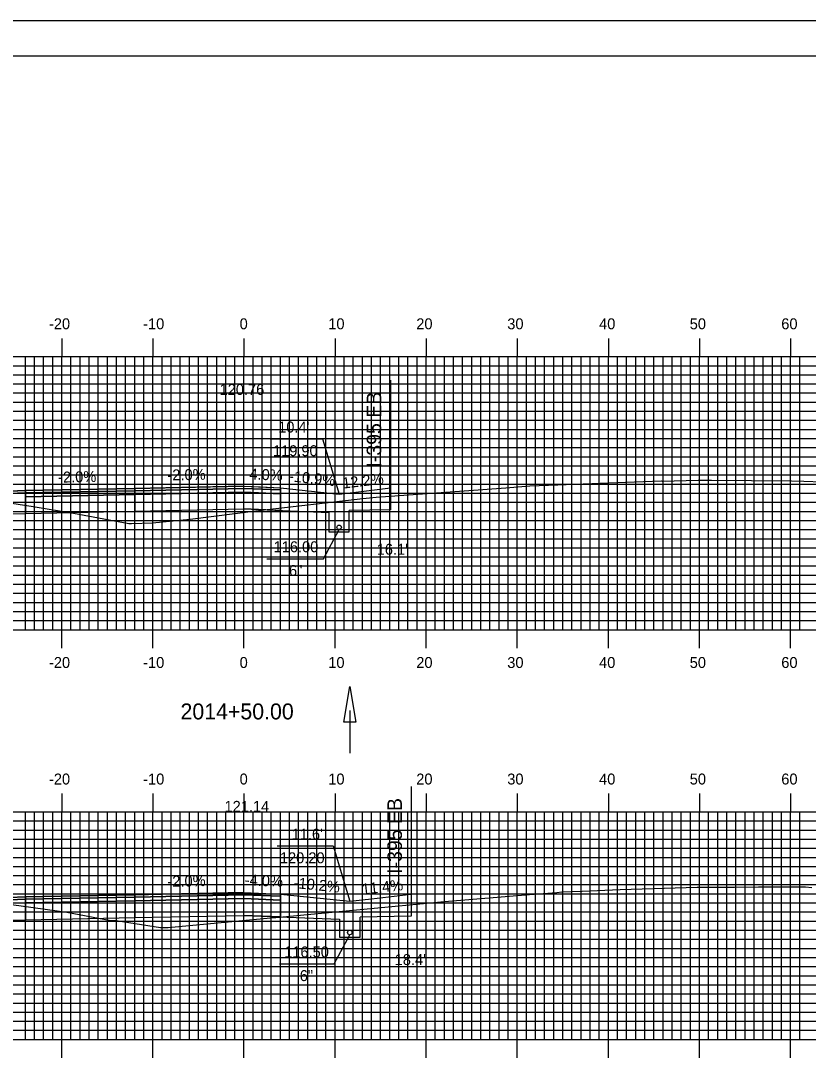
# Model space of a CAD drawing. Extents: x 854287 to 854631, y 366605 to 366825.
# Drawn here: x 854428.5 to 854515, y 366710.6 to 366824.9 of the extents above; entities that cross this region are included whole.
import ezdxf

# ---------------------------------------------------------------- set-up
doc = ezdxf.new("R2010")
doc.units = 0
for name, color, linetype in [('ANNOTATION', 7, 'Continuous'), ('BORDER', 7, 'Continuous'), ('D_Drainage_Ditch_Line', 7, 'Continuous'), ('D_Roadway_Centerline', 7, 'Continuous'), ('D_Roadway_Centerline_Text', 7, 'Continuous'), ('D_Roadway_Edge_Shoulder', 7, 'Continuous'), ('D_Roadway_Edge_TW', 7, 'Continuous'), ('D_Roadway_Pavement', 7, 'Continuous'), ('D_Roadway_SubGrade', 7, 'Continuous'), ('D_Text_Standard', 7, 'Continuous'), ('H_V ANNOTATION', 7, 'Continuous'), ('M_Roadway_Centerline', 7, 'Continuous'), ('MAJOR', 7, 'Continuous'), ('MINOR', 7, 'Continuous'), ('PDRAIN', 7, 'Continuous'), ('PLOT BOUNDARY', 7, 'Continuous'), ('S_Roadway_Centerline', 7, 'Continuous')]:
    doc.layers.add(name, color=color, linetype=linetype)

msp = doc.modelspace()

# ---------------------------------------------------------------- linework, layer by layer
at = {"layer": 'ANNOTATION'}
for points in [[(854455.93, 366779.04), (854461.66, 366779.04), (854463.48, 366772.96)], [(854455.53, 366765.85), (854461.75, 366765.85), (854463.48, 366769.06)], [(854456.69, 366734.34), (854462.84, 366734.34), (854464.66, 366728.25)], [(854456.93, 366721.35), (854462.93, 366721.35), (854464.66, 366724.56)]]:
    msp.add_lwpolyline(points, dxfattribs=at)
at = {"layer": 'BORDER'}
msp.add_lwpolyline([(854303.44, 366611.06), (854623.44, 366611.06), (854623.44, 366821.06), (854303.44, 366821.06)], close=True, dxfattribs=at)
at = {"layer": 'D_Drainage_Ditch_Line'}
msp.add_line((854464.66, 366749.2), (854464.66, 366744.5), dxfattribs=at)
msp.add_lwpolyline([(854465.32, 366747.89), (854464, 366747.89), (854464.66, 366751.83)], close=True, dxfattribs=at)
at = {"layer": 'D_Roadway_Centerline'}
for p, q in [((854453.04, 366771.32), (854462.35, 366770.95)), ((854469.12, 366771.23), (854464.6, 366771.14)), ((854453.04, 366726.69), (854463.53, 366726.27)), ((854471.39, 366726.6), (854465.78, 366726.49))]:
    msp.add_line(p, q, dxfattribs=at)
for points in [[(854370.14, 366772.7), (854370.15, 366772.7), (854406.87, 366769.48), (854410.14, 366770.29), (854410.15, 366770.29), (854421.04, 366773.02), (854421.05, 366773.02), (854423.89, 366773.13), (854429.04, 366773.34), (854429.04, 366773.34), (854441.04, 366773.58), (854441.04, 366773.58), (854449.37, 366773.75), (854453.04, 366773.82), (854454.84, 366773.75), (854457.04, 366773.66), (854463.48, 366772.96), (854463.48, 366772.96)], [(854457.04, 366773.66), (854463.48, 366772.96)], [(854463.48, 366772.96), (854465.32, 366773.18), (854469.12, 366773.65)], [(854374.32, 366728.87), (854406.87, 366724.85), (854409.62, 366725.54), (854410.14, 366725.67), (854421.04, 366728.39), (854422.63, 366728.46), (854429.04, 366728.71), (854429.04, 366728.71), (854429.05, 366728.71), (854441.04, 366728.95), (854447.09, 366729.07), (854453.04, 366729.19), (854453.58, 366729.17), (854457.04, 366729.03), (854464.66, 366728.25)], [(854457.04, 366729.03), (854464.66, 366728.25)], [(854464.66, 366728.25), (854467.03, 366728.52), (854471.39, 366729.02)]]:
    msp.add_lwpolyline(points, dxfattribs=at)
at = {"layer": 'D_Roadway_Edge_Shoulder'}
for points in [[(854453.04, 366773.82), (854457.04, 366773.66), (854457.04, 366773.41), (854453.04, 366773.57)], [(854429.04, 366773.34), (854421.04, 366773.02), (854421.04, 366772.77), (854429.04, 366773.09)], [(854453.04, 366729.19), (854457.04, 366729.03), (854457.04, 366728.78), (854453.04, 366728.94)], [(854429.04, 366728.71), (854421.04, 366728.39), (854421.04, 366728.14), (854429.04, 366728.46)]]:
    msp.add_lwpolyline(points, close=True, dxfattribs=at)
at = {"layer": 'D_Roadway_Edge_TW'}
for points in [[(854453.04, 366773.82), (854441.04, 366773.58), (854441.04, 366773.33), (854453.04, 366773.57)], [(854441.04, 366773.58), (854429.04, 366773.34), (854429.04, 366773.09), (854441.04, 366773.33)], [(854453.04, 366729.19), (854441.04, 366728.95), (854441.04, 366728.7), (854453.04, 366728.94)], [(854441.04, 366728.95), (854429.04, 366728.71), (854429.04, 366728.46), (854441.04, 366728.7)]]:
    msp.add_lwpolyline(points, close=True, dxfattribs=at)
at = {"layer": 'D_Roadway_Pavement'}
for points in [[(854441.04, 366773.33), (854429.04, 366773.09), (854429.04, 366772.67), (854441.04, 366772.91)], [(854453.04, 366773.57), (854441.04, 366773.33), (854441.04, 366772.91), (854453.04, 366773.15)], [(854453.04, 366773.57), (854457.04, 366773.41), (854457.04, 366772.99), (854453.04, 366773.15)], [(854441.04, 366728.7), (854429.04, 366728.46), (854429.04, 366728.05), (854441.04, 366728.29)], [(854453.04, 366728.94), (854441.04, 366728.7), (854441.04, 366728.29), (854453.04, 366728.53)], [(854453.04, 366728.94), (854457.04, 366728.78), (854457.04, 366728.37), (854453.04, 366728.53)]]:
    msp.add_lwpolyline(points, close=True, dxfattribs=at)
for points in [[(854429.04, 366773.09), (854429.04, 366772.67)], [(854429.04, 366773.09), (854429.04, 366772.67)], [(854441.04, 366773.33), (854441.04, 366772.91)], [(854429.04, 366728.46), (854429.04, 366728.05)], [(854429.04, 366728.46), (854429.04, 366728.05)], [(854441.04, 366728.7), (854441.04, 366728.29)]]:
    msp.add_lwpolyline(points, dxfattribs=at)
at = {"layer": 'D_Roadway_SubGrade'}
for p, q in [((854469.12, 366785.46), (854469.12, 366771.23)), ((854471.39, 366740.83), (854471.39, 366726.6))]:
    msp.add_line(p, q, dxfattribs=at)
for points in [[(854453.04, 366773.15), (854457.04, 366772.99), (854457.04, 366773.41), (854457.04, 366773.66), (854457.04, 366771.16), (854453.04, 366771.32)], [(854429.04, 366772.67), (854429.04, 366773.09), (854421.04, 366772.77), (854421.04, 366773.02), (854410.87, 366770.48), (854429.04, 366770.84)], [(854441.04, 366772.91), (854429.04, 366772.67), (854429.04, 366770.84), (854441.04, 366771.08)], [(854453.04, 366773.15), (854441.04, 366772.91), (854441.04, 366771.08), (854453.04, 366771.32)], [(854453.04, 366728.53), (854457.04, 366728.37), (854457.04, 366728.78), (854457.04, 366729.03), (854457.04, 366726.53), (854453.04, 366726.69)], [(854429.04, 366728.05), (854429.04, 366728.46), (854421.04, 366728.14), (854421.04, 366728.39), (854410.87, 366725.85), (854429.04, 366726.21)], [(854441.04, 366728.29), (854429.04, 366728.05), (854429.04, 366726.21), (854441.04, 366726.45)], [(854453.04, 366728.53), (854441.04, 366728.29), (854441.04, 366726.45), (854453.04, 366726.69)]]:
    msp.add_lwpolyline(points, close=True, dxfattribs=at)
at = {"layer": 'MAJOR'}
for p, q in [((854433.04, 366790.06), (854433.04, 366788.06)), ((854443.04, 366790.06), (854443.04, 366788.06)), ((854453.04, 366790.06), (854453.04, 366788.06)), ((854463.04, 366790.06), (854463.04, 366788.06)), ((854473.04, 366790.06), (854473.04, 366788.06)), ((854483.04, 366790.06), (854483.04, 366788.06)), ((854493.04, 366790.06), (854493.04, 366788.06)), ((854503.04, 366790.06), (854503.04, 366788.06)), ((854513.04, 366790.06), (854513.04, 366788.06)), ((854313.04, 366788.06), (854593.04, 366788.06)), ((854313.04, 366788.06), (854593.04, 366788.06)), ((854433.04, 366758.06), (854433.04, 366788.06)), ((854443.04, 366758.06), (854443.04, 366788.06)), ((854453.04, 366758.06), (854453.04, 366788.06)), ((854463.04, 366758.06), (854463.04, 366788.06)), ((854473.04, 366758.06), (854473.04, 366788.06)), ((854483.04, 366758.06), (854483.04, 366788.06)), ((854493.04, 366758.06), (854493.04, 366788.06)), ((854503.04, 366758.06), (854503.04, 366788.06)), ((854513.04, 366758.06), (854513.04, 366788.06)), ((854313.04, 366783.06), (854593.04, 366783.06)), ((854313.04, 366778.06), (854593.04, 366778.06)), ((854313.04, 366773.06), (854593.04, 366773.06)), ((854313.04, 366768.06), (854593.04, 366768.06)), ((854313.04, 366763.06), (854593.04, 366763.06)), ((854313.04, 366758.06), (854593.04, 366758.06)), ((854313.04, 366758.06), (854593.04, 366758.06)), ((854433.04, 366756.05), (854433.04, 366758.06)), ((854443.04, 366756.05), (854443.04, 366758.06)), ((854453.04, 366756.05), (854453.04, 366758.06)), ((854463.04, 366756.05), (854463.04, 366758.06)), ((854473.04, 366756.05), (854473.04, 366758.06)), ((854483.04, 366756.05), (854483.04, 366758.06)), ((854493.04, 366756.05), (854493.04, 366758.06)), ((854503.04, 366756.05), (854503.04, 366758.06)), ((854513.04, 366756.05), (854513.04, 366758.06)), ((854433.04, 366740.06), (854433.04, 366738.06)), ((854443.04, 366740.06), (854443.04, 366738.06)), ((854453.04, 366740.06), (854453.04, 366738.06)), ((854463.04, 366740.06), (854463.04, 366738.06)), ((854473.04, 366740.06), (854473.04, 366738.06)), ((854483.04, 366740.06), (854483.04, 366738.06)), ((854493.04, 366740.06), (854493.04, 366738.06)), ((854503.04, 366740.06), (854503.04, 366738.06)), ((854513.04, 366740.06), (854513.04, 366738.06)), ((854313.04, 366738.06), (854593.04, 366738.06)), ((854313.04, 366738.06), (854593.04, 366738.06)), ((854433.04, 366713.06), (854433.04, 366738.06)), ((854443.04, 366713.06), (854443.04, 366738.06)), ((854453.04, 366713.06), (854453.04, 366738.06)), ((854463.04, 366713.06), (854463.04, 366738.06)), ((854473.04, 366713.06), (854473.04, 366738.06)), ((854483.04, 366713.06), (854483.04, 366738.06)), ((854493.04, 366713.06), (854493.04, 366738.06)), ((854503.04, 366713.06), (854503.04, 366738.06)), ((854513.04, 366713.06), (854513.04, 366738.06)), ((854313.04, 366733.06), (854593.04, 366733.06)), ((854313.04, 366728.06), (854593.04, 366728.06)), ((854313.04, 366723.06), (854593.04, 366723.06)), ((854313.04, 366718.06), (854593.04, 366718.06)), ((854313.04, 366713.06), (854593.04, 366713.06)), ((854313.04, 366713.06), (854593.04, 366713.06)), ((854433.04, 366711.05), (854433.04, 366713.06)), ((854443.04, 366711.05), (854443.04, 366713.06)), ((854453.04, 366711.05), (854453.04, 366713.06)), ((854463.04, 366711.05), (854463.04, 366713.06)), ((854473.04, 366711.05), (854473.04, 366713.06)), ((854483.04, 366711.05), (854483.04, 366713.06)), ((854493.04, 366711.05), (854493.04, 366713.06)), ((854503.04, 366711.05), (854503.04, 366713.06)), ((854513.04, 366711.05), (854513.04, 366713.06))]:
    msp.add_line(p, q, dxfattribs=at)
at = {"layer": 'MINOR'}
for p, q in [((854429.04, 366758.06), (854429.04, 366788.06)), ((854430.04, 366758.06), (854430.04, 366788.06)), ((854431.04, 366758.06), (854431.04, 366788.06)), ((854432.04, 366758.06), (854432.04, 366788.06)), ((854434.04, 366758.06), (854434.04, 366788.06)), ((854435.04, 366758.06), (854435.04, 366788.06)), ((854436.04, 366758.06), (854436.04, 366788.06)), ((854437.04, 366758.06), (854437.04, 366788.06)), ((854438.04, 366758.06), (854438.04, 366788.06)), ((854439.04, 366758.06), (854439.04, 366788.06)), ((854440.04, 366758.06), (854440.04, 366788.06)), ((854441.04, 366758.06), (854441.04, 366788.06)), ((854442.04, 366758.06), (854442.04, 366788.06)), ((854444.04, 366758.06), (854444.04, 366788.06)), ((854445.04, 366758.06), (854445.04, 366788.06)), ((854446.04, 366758.06), (854446.04, 366788.06)), ((854447.04, 366758.06), (854447.04, 366788.06)), ((854448.04, 366758.06), (854448.04, 366788.06)), ((854449.04, 366758.06), (854449.04, 366788.06)), ((854450.04, 366758.06), (854450.04, 366788.06)), ((854451.04, 366758.06), (854451.04, 366788.06)), ((854452.04, 366758.06), (854452.04, 366788.06)), ((854454.04, 366758.06), (854454.04, 366788.06)), ((854455.04, 366758.06), (854455.04, 366788.06)), ((854456.04, 366758.06), (854456.04, 366788.06)), ((854457.04, 366758.06), (854457.04, 366788.06)), ((854458.04, 366758.06), (854458.04, 366788.06)), ((854459.04, 366758.06), (854459.04, 366788.06)), ((854460.04, 366758.06), (854460.04, 366788.06)), ((854461.04, 366758.06), (854461.04, 366788.06)), ((854462.04, 366758.06), (854462.04, 366788.06)), ((854464.04, 366758.06), (854464.04, 366788.06)), ((854465.04, 366758.06), (854465.04, 366788.06)), ((854466.04, 366758.06), (854466.04, 366788.06)), ((854467.04, 366758.06), (854467.04, 366788.06)), ((854468.04, 366758.06), (854468.04, 366788.06)), ((854469.04, 366758.06), (854469.04, 366788.06)), ((854470.04, 366758.06), (854470.04, 366788.06)), ((854471.04, 366758.06), (854471.04, 366788.06)), ((854472.04, 366758.06), (854472.04, 366788.06)), ((854474.04, 366758.06), (854474.04, 366788.06)), ((854475.04, 366758.06), (854475.04, 366788.06)), ((854476.04, 366758.06), (854476.04, 366788.06)), ((854477.04, 366758.06), (854477.04, 366788.06)), ((854478.04, 366758.06), (854478.04, 366788.06)), ((854479.04, 366758.06), (854479.04, 366788.06)), ((854480.04, 366758.06), (854480.04, 366788.06)), ((854481.04, 366758.06), (854481.04, 366788.06)), ((854482.04, 366758.06), (854482.04, 366788.06)), ((854484.04, 366758.06), (854484.04, 366788.06)), ((854485.04, 366758.06), (854485.04, 366788.06)), ((854486.04, 366758.06), (854486.04, 366788.06)), ((854487.04, 366758.06), (854487.04, 366788.06)), ((854488.04, 366758.06), (854488.04, 366788.06)), ((854489.04, 366758.06), (854489.04, 366788.06)), ((854490.04, 366758.06), (854490.04, 366788.06)), ((854491.04, 366758.06), (854491.04, 366788.06)), ((854492.04, 366758.06), (854492.04, 366788.06)), ((854494.04, 366758.06), (854494.04, 366788.06)), ((854495.04, 366758.06), (854495.04, 366788.06)), ((854496.04, 366758.06), (854496.04, 366788.06)), ((854497.04, 366758.06), (854497.04, 366788.06)), ((854498.04, 366758.06), (854498.04, 366788.06)), ((854499.04, 366758.06), (854499.04, 366788.06)), ((854500.04, 366758.06), (854500.04, 366788.06)), ((854501.04, 366758.06), (854501.04, 366788.06)), ((854502.04, 366758.06), (854502.04, 366788.06)), ((854504.04, 366758.06), (854504.04, 366788.06)), ((854505.04, 366758.06), (854505.04, 366788.06)), ((854506.04, 366758.06), (854506.04, 366788.06)), ((854507.04, 366758.06), (854507.04, 366788.06)), ((854508.04, 366758.06), (854508.04, 366788.06)), ((854509.04, 366758.06), (854509.04, 366788.06)), ((854510.04, 366758.06), (854510.04, 366788.06)), ((854511.04, 366758.06), (854511.04, 366788.06)), ((854512.04, 366758.06), (854512.04, 366788.06)), ((854514.04, 366758.06), (854514.04, 366788.06)), ((854313.04, 366787.06), (854593.04, 366787.06)), ((854313.04, 366786.06), (854593.04, 366786.06)), ((854313.04, 366785.06), (854593.04, 366785.06)), ((854313.04, 366784.06), (854593.04, 366784.06)), ((854313.04, 366782.06), (854593.04, 366782.06)), ((854313.04, 366781.06), (854593.04, 366781.06)), ((854313.04, 366780.06), (854593.04, 366780.06)), ((854313.04, 366779.06), (854593.04, 366779.06)), ((854313.04, 366777.06), (854593.04, 366777.06)), ((854313.04, 366776.06), (854593.04, 366776.06)), ((854313.04, 366775.06), (854593.04, 366775.06)), ((854313.04, 366774.06), (854593.04, 366774.06)), ((854313.04, 366772.06), (854593.04, 366772.06)), ((854313.04, 366771.06), (854593.04, 366771.06)), ((854313.04, 366770.06), (854593.04, 366770.06)), ((854313.04, 366769.06), (854593.04, 366769.06)), ((854313.04, 366767.06), (854593.04, 366767.06)), ((854313.04, 366766.06), (854593.04, 366766.06)), ((854313.04, 366765.06), (854593.04, 366765.06)), ((854313.04, 366764.06), (854593.04, 366764.06)), ((854313.04, 366762.06), (854593.04, 366762.06)), ((854313.04, 366761.06), (854593.04, 366761.06)), ((854313.04, 366760.06), (854593.04, 366760.06)), ((854313.04, 366759.06), (854593.04, 366759.06)), ((854313.04, 366737.06), (854593.04, 366737.06)), ((854429.04, 366713.06), (854429.04, 366738.06)), ((854430.04, 366713.06), (854430.04, 366738.06)), ((854431.04, 366713.06), (854431.04, 366738.06)), ((854432.04, 366713.06), (854432.04, 366738.06)), ((854434.04, 366713.06), (854434.04, 366738.06)), ((854435.04, 366713.06), (854435.04, 366738.06)), ((854436.04, 366713.06), (854436.04, 366738.06)), ((854437.04, 366713.06), (854437.04, 366738.06)), ((854438.04, 366713.06), (854438.04, 366738.06)), ((854439.04, 366713.06), (854439.04, 366738.06)), ((854440.04, 366713.06), (854440.04, 366738.06)), ((854441.04, 366713.06), (854441.04, 366738.06)), ((854442.04, 366713.06), (854442.04, 366738.06)), ((854444.04, 366713.06), (854444.04, 366738.06)), ((854445.04, 366713.06), (854445.04, 366738.06)), ((854446.04, 366713.06), (854446.04, 366738.06)), ((854447.04, 366713.06), (854447.04, 366738.06)), ((854448.04, 366713.06), (854448.04, 366738.06)), ((854449.04, 366713.06), (854449.04, 366738.06)), ((854450.04, 366713.06), (854450.04, 366738.06)), ((854451.04, 366713.06), (854451.04, 366738.06)), ((854452.04, 366713.06), (854452.04, 366738.06)), ((854454.04, 366713.06), (854454.04, 366738.06)), ((854455.04, 366713.06), (854455.04, 366738.06)), ((854456.04, 366713.06), (854456.04, 366738.06)), ((854457.04, 366713.06), (854457.04, 366738.06)), ((854458.04, 366713.06), (854458.04, 366738.06)), ((854459.04, 366713.06), (854459.04, 366738.06)), ((854460.04, 366713.06), (854460.04, 366738.06)), ((854461.04, 366713.06), (854461.04, 366738.06)), ((854462.04, 366713.06), (854462.04, 366738.06)), ((854464.04, 366713.06), (854464.04, 366738.06)), ((854465.04, 366713.06), (854465.04, 366738.06)), ((854466.04, 366713.06), (854466.04, 366738.06)), ((854467.04, 366713.06), (854467.04, 366738.06)), ((854468.04, 366713.06), (854468.04, 366738.06)), ((854469.04, 366713.06), (854469.04, 366738.06)), ((854470.04, 366713.06), (854470.04, 366738.06)), ((854471.04, 366713.06), (854471.04, 366738.06)), ((854472.04, 366713.06), (854472.04, 366738.06)), ((854474.04, 366713.06), (854474.04, 366738.06)), ((854475.04, 366713.06), (854475.04, 366738.06)), ((854476.04, 366713.06), (854476.04, 366738.06)), ((854477.04, 366713.06), (854477.04, 366738.06)), ((854478.04, 366713.06), (854478.04, 366738.06)), ((854479.04, 366713.06), (854479.04, 366738.06)), ((854480.04, 366713.06), (854480.04, 366738.06)), ((854481.04, 366713.06), (854481.04, 366738.06)), ((854482.04, 366713.06), (854482.04, 366738.06)), ((854484.04, 366713.06), (854484.04, 366738.06)), ((854485.04, 366713.06), (854485.04, 366738.06)), ((854486.04, 366713.06), (854486.04, 366738.06)), ((854487.04, 366713.06), (854487.04, 366738.06)), ((854488.04, 366713.06), (854488.04, 366738.06)), ((854489.04, 366713.06), (854489.04, 366738.06)), ((854490.04, 366713.06), (854490.04, 366738.06)), ((854491.04, 366713.06), (854491.04, 366738.06)), ((854492.04, 366713.06), (854492.04, 366738.06)), ((854494.04, 366713.06), (854494.04, 366738.06)), ((854495.04, 366713.06), (854495.04, 366738.06)), ((854496.04, 366713.06), (854496.04, 366738.06)), ((854497.04, 366713.06), (854497.04, 366738.06)), ((854498.04, 366713.06), (854498.04, 366738.06)), ((854499.04, 366713.06), (854499.04, 366738.06)), ((854500.04, 366713.06), (854500.04, 366738.06)), ((854501.04, 366713.06), (854501.04, 366738.06)), ((854502.04, 366713.06), (854502.04, 366738.06)), ((854504.04, 366713.06), (854504.04, 366738.06)), ((854505.04, 366713.06), (854505.04, 366738.06)), ((854506.04, 366713.06), (854506.04, 366738.06)), ((854507.04, 366713.06), (854507.04, 366738.06)), ((854508.04, 366713.06), (854508.04, 366738.06)), ((854509.04, 366713.06), (854509.04, 366738.06)), ((854510.04, 366713.06), (854510.04, 366738.06)), ((854511.04, 366713.06), (854511.04, 366738.06)), ((854512.04, 366713.06), (854512.04, 366738.06)), ((854514.04, 366713.06), (854514.04, 366738.06)), ((854313.04, 366736.06), (854593.04, 366736.06)), ((854313.04, 366735.06), (854593.04, 366735.06)), ((854313.04, 366734.06), (854593.04, 366734.06)), ((854313.04, 366732.06), (854593.04, 366732.06)), ((854313.04, 366731.06), (854593.04, 366731.06)), ((854313.04, 366730.06), (854593.04, 366730.06)), ((854313.04, 366729.06), (854593.04, 366729.06)), ((854313.04, 366727.06), (854593.04, 366727.06)), ((854313.04, 366726.06), (854593.04, 366726.06)), ((854313.04, 366725.06), (854593.04, 366725.06)), ((854313.04, 366724.06), (854593.04, 366724.06)), ((854313.04, 366722.06), (854593.04, 366722.06)), ((854313.04, 366721.06), (854593.04, 366721.06)), ((854313.04, 366720.06), (854593.04, 366720.06)), ((854313.04, 366719.06), (854593.04, 366719.06)), ((854313.04, 366717.06), (854593.04, 366717.06)), ((854313.04, 366716.06), (854593.04, 366716.06)), ((854313.04, 366715.06), (854593.04, 366715.06)), ((854313.04, 366714.06), (854593.04, 366714.06))]:
    msp.add_line(p, q, dxfattribs=at)
at = {"layer": 'PDRAIN'}
for points in [[(854462.35, 366770.95), (854462.35, 366768.81), (854464.6, 366768.81), (854464.6, 366771.14)], [(854463.53, 366726.27), (854463.53, 366724.31), (854465.78, 366724.31), (854465.78, 366726.49)]]:
    msp.add_lwpolyline(points, dxfattribs=at)
for centre in [(854463.48, 366769.31), (854464.66, 366724.81)]:
    msp.add_circle(centre, 0.25, dxfattribs=at)
at = {"layer": 'PLOT BOUNDARY'}
msp.add_lwpolyline([(854287.26, 366604.94), (854627.26, 366604.94), (854627.26, 366824.94), (854287.26, 366824.94)], close=True, dxfattribs=at)
at = {"layer": 'S_Roadway_Centerline'}
for points in [[(854417.65, 366773.49), (854429.9, 366771.61), (854434.31, 366770.85), (854440.41, 366769.73), (854440.69, 366769.72), (854443, 366769.8), (854447.14, 366770.22), (854454.63, 366771.14), (854466.08, 366772.49), (854467.54, 366772.61), (854481.79, 366773.65), (854484.43, 366773.85), (854487.48, 366773.96), (854494.92, 366774.25), (854498.86, 366774.41), (854498.95, 366774.39), (854502.89, 366774.48), (854504.36, 366774.48), (854513.14, 366774.4), (854514.48, 366774.37), (854516.5, 366774.3)], [(854423.8, 366728.39), (854433.58, 366727.02), (854438.43, 366726.14), (854439, 366726.12), (854443.86, 366725.35), (854444.72, 366725.35), (854455.58, 366726.37), (854455.98, 366726.41), (854456.54, 366726.46), (854475.04, 366728.21), (854484.38, 366728.98), (854487.39, 366729.21), (854487.94, 366729.26), (854490.15, 366729.35), (854494.35, 366729.51), (854502.78, 366729.78), (854503.35, 366729.8), (854506.88, 366729.8), (854509.53, 366729.81), (854514.68, 366729.82), (854515.38, 366729.76)]]:
    msp.add_lwpolyline(points, dxfattribs=at)

# ---------------------------------------------------------------- texts
at = {"layer": 'ANNOTATION'}
for s, height, rotation, p in [('I-395 EB', 1.6, 90, (854468.11, 366775.87)), ('-2.0%', 1.2, 1.1458, (854432.65, 366774.21)), ('-2.0%', 1.2, 1.1457, (854444.65, 366774.45)), ('-4.0%', 1.2, 357.7093, (854453.08, 366774.59)), ('-10.9%', 1.2, 353.7737, (854457.93, 366774.37)), ('12.2%', 1.2, 6.9734, (854463.91, 366773.55)), ('116.00', 1.2, 360, (854456.29, 366766.57)), ('6"', 1.2, 360, (854457.98, 366763.97)), ('I-395 EB', 1.6, 90, (854470.38, 366731.25)), ('-2.0%', 1.2, 1.1458, (854444.65, 366729.82)), ('-4.0%', 1.2, 357.7093, (854453.1, 366729.99)), ('-10.2%', 1.2, 354.1602, (854458.45, 366729.7)), ('11.4%', 1.2, 6.5137, (854466.04, 366728.95)), ('116.50', 1.2, 360, (854457.45, 366722.07)), ('6"', 1.2, 360, (854459.16, 366719.47))]:
    msp.add_text(s, height=height, rotation=rotation, dxfattribs=at).set_placement(p)
for s, p in [("10.4' ", (854456.79, 366779.72)), ('119.90', (854456.22, 366777.12)), ("11.6' ", (854458.27, 366735.01)), ('120.20', (854456.98, 366732.41))]:
    msp.add_text(s, height=1.2, dxfattribs=at).set_placement(p)
at = {"layer": 'D_Roadway_Centerline_Text'}
for s, p in [('120.76', (854450.36, 366783.85)), ('121.14', (854450.9, 366738.06))]:
    msp.add_text(s, height=1.2, dxfattribs=at).set_placement(p)
at = {"layer": 'D_Text_Standard'}
for s, p in [("16.1'", (854467.61, 366766.3)), ("18.4'", (854469.58, 366721.23))]:
    msp.add_text(s, height=1.2, dxfattribs=at).set_placement(p)
at = {"layer": 'H_V ANNOTATION'}
for s, height, p in [('-20', 1.2, (854431.63, 366791.06)), ('-10', 1.2, (854441.97, 366791.06)), ('0', 1.2, (854452.56, 366791.06)), ('10', 1.2, (854462.29, 366791.06)), ('20', 1.2, (854471.95, 366791.06)), ('30', 1.2, (854481.94, 366791.06)), ('40', 1.2, (854492.02, 366791.06)), ('50', 1.2, (854501.97, 366791.06)), ('60', 1.2, (854512.02, 366791.06)), ('-20', 1.2, (854431.63, 366753.86)), ('-10', 1.2, (854441.97, 366753.86)), ('0', 1.2, (854452.56, 366753.86)), ('10', 1.2, (854462.29, 366753.86)), ('20', 1.2, (854471.95, 366753.86)), ('30', 1.2, (854481.94, 366753.86)), ('40', 1.2, (854492.02, 366753.86)), ('50', 1.2, (854501.97, 366753.86)), ('60', 1.2, (854512.02, 366753.86)), ('2014+50.00', 1.75, (854446.07, 366748.21)), ('-20', 1.2, (854431.63, 366741.06)), ('-10', 1.2, (854441.97, 366741.06)), ('0', 1.2, (854452.56, 366741.06)), ('10', 1.2, (854462.29, 366741.06)), ('20', 1.2, (854471.95, 366741.06)), ('30', 1.2, (854481.94, 366741.06)), ('40', 1.2, (854492.02, 366741.06)), ('50', 1.2, (854501.97, 366741.06)), ('60', 1.2, (854512.02, 366741.06))]:
    msp.add_text(s, height=height, dxfattribs=at).set_placement(p)
at = {"layer": 'M_Roadway_Centerline'}
for s, p in [('C', (854498.85, 366774.41)), ('L', (854498.86, 366774.4)), ('C', (854514.47, 366774.37)), ('L', (854514.48, 366774.36)), ('C', (854503.35, 366729.8)), ('L', (854503.35, 366729.79)), ('C', (854514.68, 366729.82)), ('L', (854514.68, 366729.82))]:
    msp.add_text(s, height=0.0146, dxfattribs=at).set_placement(p)

doc.saveas('drawing.dxf')
